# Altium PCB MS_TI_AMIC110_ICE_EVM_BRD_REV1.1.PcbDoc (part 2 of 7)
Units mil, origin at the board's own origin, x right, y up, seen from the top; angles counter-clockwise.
Board outline 3464.57 x 2204.72 mil, 8 copper layers (TopLayer - S1 (.GTL), MidLayer1 - S2 (.G1), MidLayer2 - S3 (.G2), MidLayer3 - S4 (.G3), MidLayer4 - S5 (.G4), MidLayer5 - S6 (.G5), MidLayer6 - S7 (.G6), BottomLayer - S8 (.GBL)), stack 58.937 mil thick; 504 components, 369 nets, 1811 pads, 874 vias.
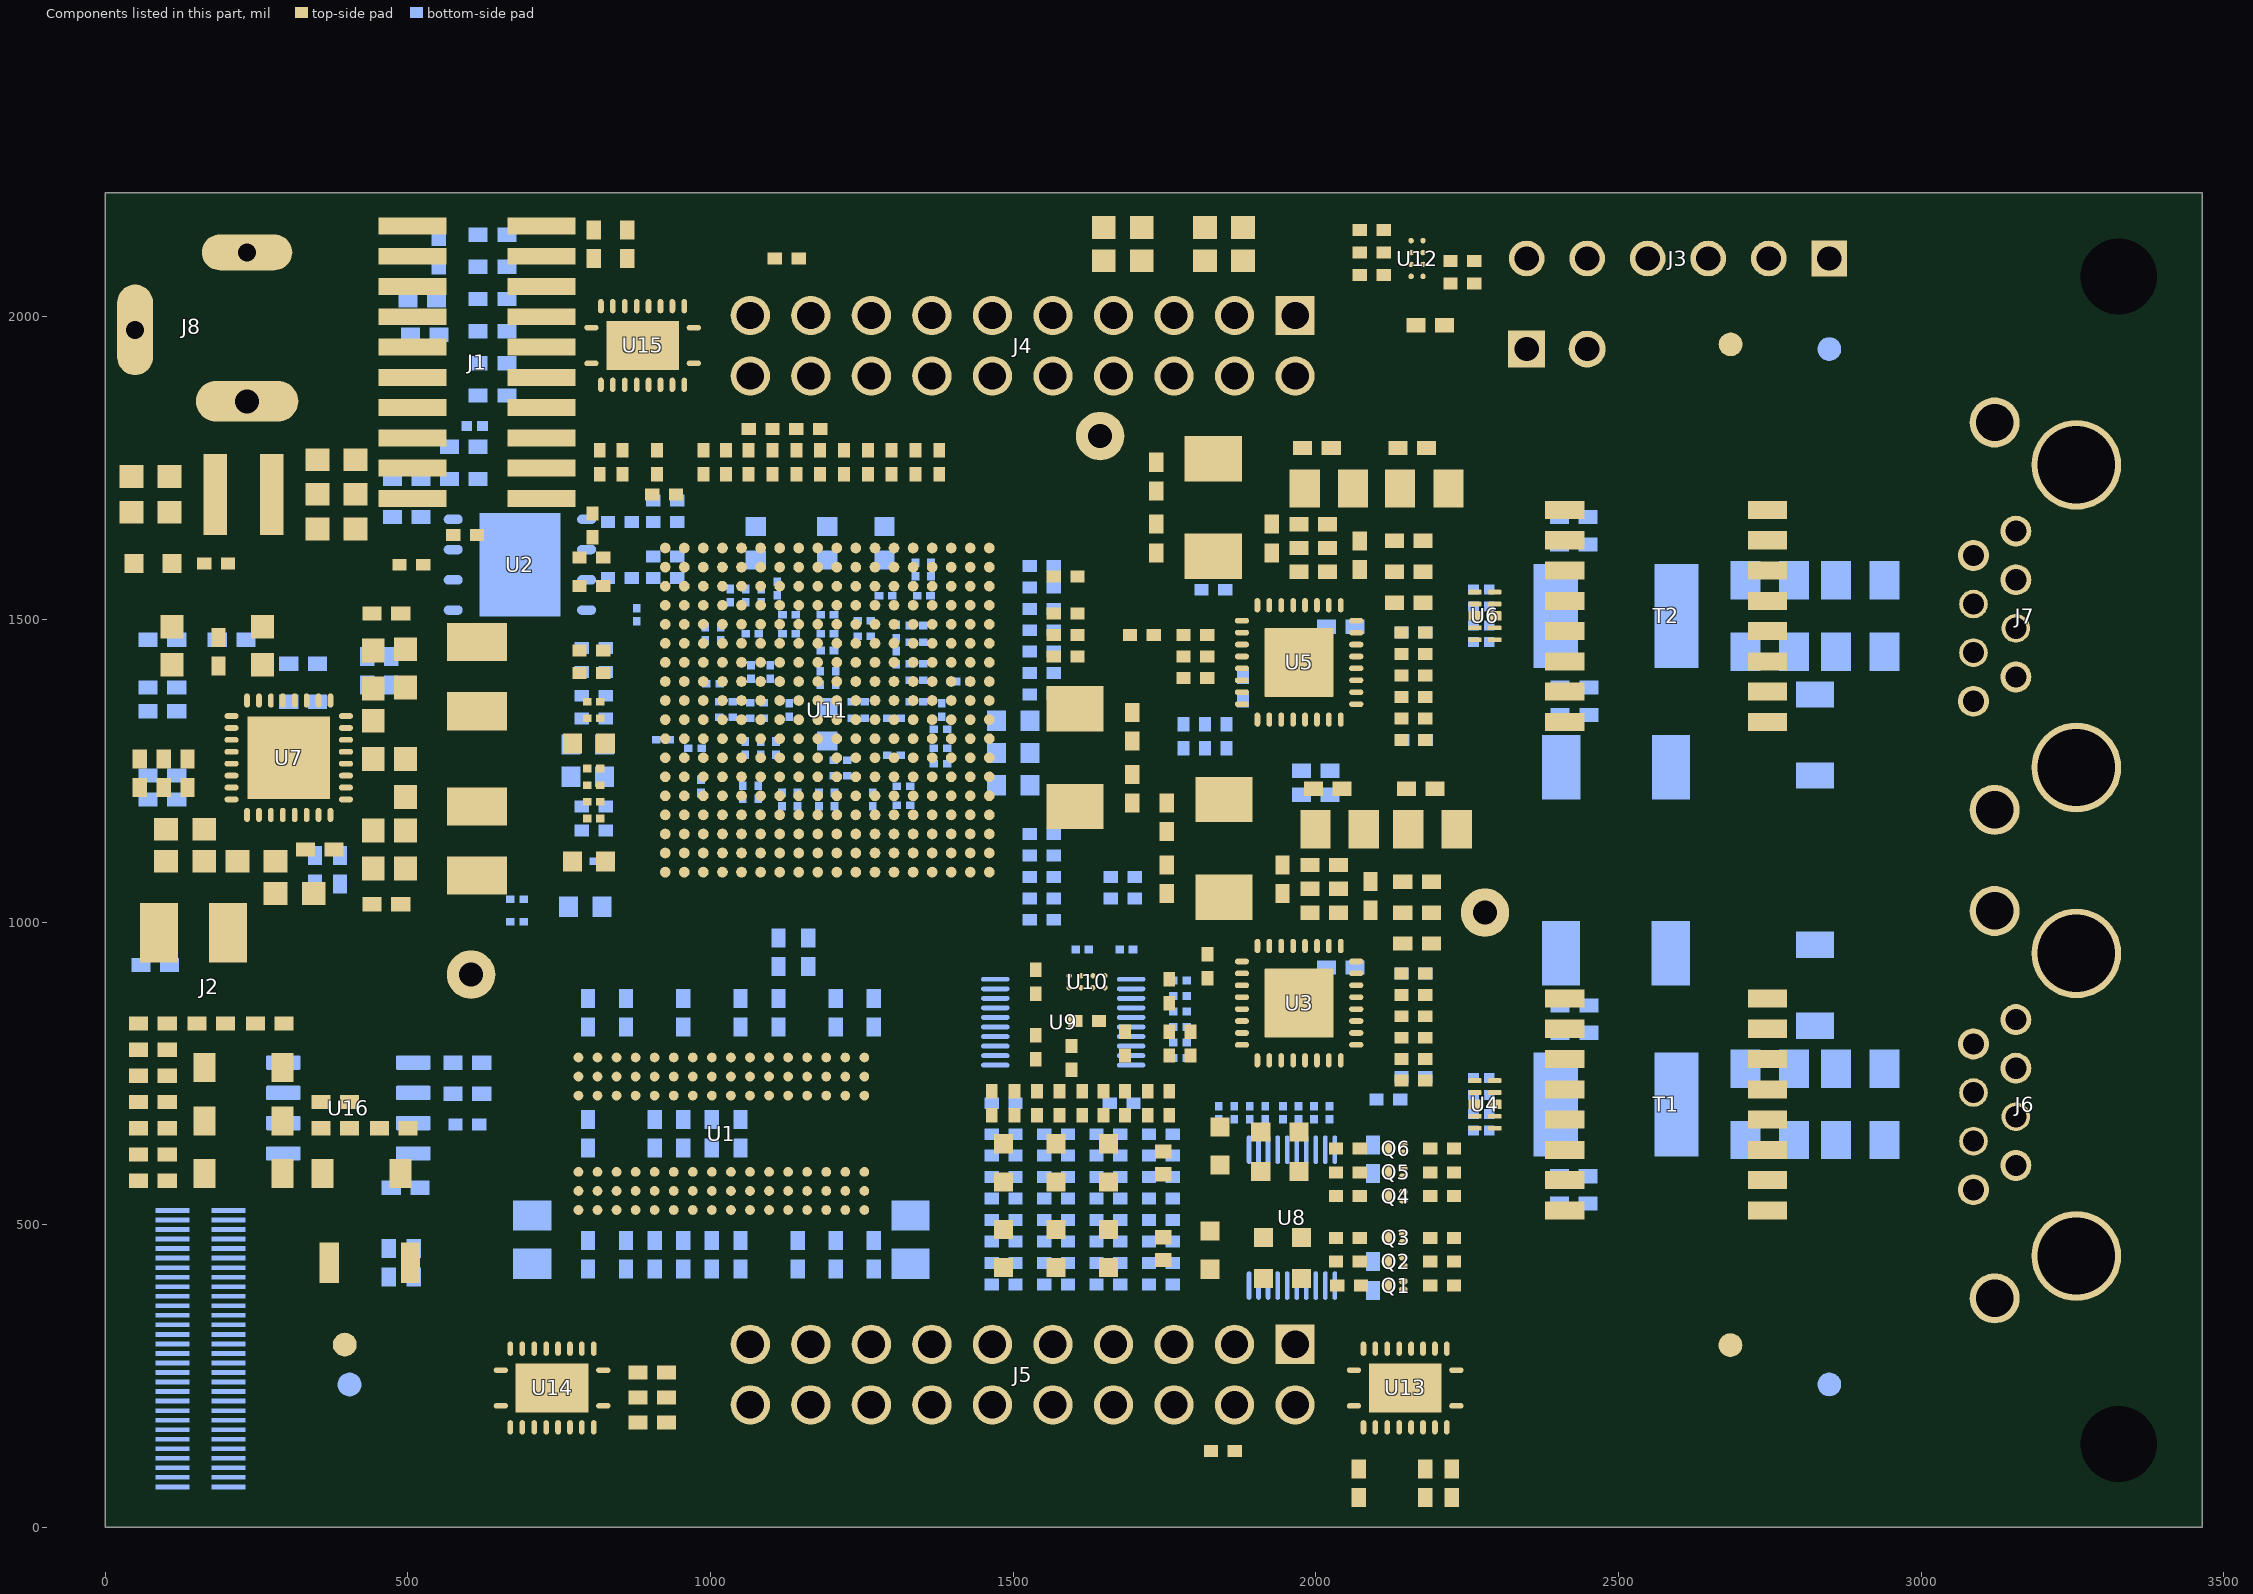
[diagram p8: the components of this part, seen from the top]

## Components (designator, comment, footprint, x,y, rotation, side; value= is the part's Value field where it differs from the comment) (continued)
R119 "CRCW040210K0JNED" 0402 2094.49,415.35 r270 bottom value=10k
R120 "CRCW040210K0JNED" 0402L 1484.25,700.79 r180 bottom value=10k
R121 "CRCW040210K0JNED" 0402L 1537.4,901.57 r90 top value=10k
R122 "CRCW0402100KJNED" 0402L 1570.87,401.57 r180 bottom value=100k
R123 "CRCW0402100KJNED" 0402L 1657.48,401.57 r0 bottom value=100k
R124 "CRCW0402100KJNED" 0402L 1570.87,437.01 r180 bottom value=100k
R125 "CRCW0402100KJNED" 0402L 1657.48,437.01 r0 bottom value=100k
R126 "CRCW0402100KJNED" 0402L 1570.87,472.44 r180 bottom value=100k
R127 "CRCW0402100KJNED" 0402L 1657.48,472.44 r0 bottom value=100k
R128 "CRCW0402100KJNED" 0402L 1570.87,507.87 r180 bottom value=100k
R129 "CRCW0402100KJNED" 0402L 1657.48,507.87 r0 bottom value=100k
R130 "CRCW0402100KJNED" 0402L 1570.87,543.31 r180 bottom value=100k
R131 "CRCW0402100KJNED" 0402L 1657.48,543.31 r0 bottom value=100k
R132 "CRCW0402100KJNED" 0402L 1570.87,578.74 r180 bottom value=100k
R133 "CRCW0402100KJNED" 0402L 1657.48,578.74 r0 bottom value=100k
R134 "CRCW0402100KJNED" 0402L 1570.87,614.17 r180 bottom value=100k
R135 "CRCW0402100KJNED" 0402L 1657.48,614.17 r0 bottom value=100k
R136 "CRCW0402100KJNED" 0402L 1570.87,649.61 r180 bottom value=100k
R137 "CRCW0402100KJNED" 0402L 1657.48,649.61 r0 bottom value=100k
R138 "CRCW040210K0JNED" 0402L 807.09,1374.02 r180 bottom value=10k
R139 "CRCW04020000Z0ED" 0402L 1220.47,1759.84 r90 top value=0
R140 "CRCW040222R0JNED" 0402L 1259.84,1759.84 r90 top value=22
R141 "CRCW040210K0JNED" 0402L 807.09,1151.57 r0 bottom value=10k
R142 "CRCW040210K0JNED" 0402L 807.09,1190.94 r0 bottom value=10k
R143 "CRCW04020000Z0ED" 0402L 1299.21,1759.84 r90 top value=0
R144 "CRCW04020000Z0ED" 0402L 1025.59,1759.84 r90 top value=0
R145 "CRCW040247R0JNED" 0402L 1141.73,1759.84 r90 top value=47
R146 "CRCW04020000Z0ED" 0402L 1338.58,1759.84 r90 top value=0
R147 "CRCW040222R0JNED" 0402L 1062.99,1759.84 r90 top value=22
R148 "CRCW040222R0JNED" 0402L 1181.1,1759.84 r90 top value=22
R149 "CRCW040247R0JNED" 0402L 803.15,1602.36 r0 top value=47
R150 "CRCW040222R0JNED" 0402L 1586.61,1474.41 r180 top value=22
R151 "CRCW04020000Z0ED" 0402L 1102.36,1759.84 r90 top value=0
R152 "CRCW04020000Z0ED" 0402L 803.15,1555.12 r0 top value=0
R153 "CRCW040222R0JNED" 0402L 1586.61,1509.84 r180 top value=22
R154 "CRCW04020000Z0ED" 0402L 1547.24,1003.94 r0 bottom value=0
R155 "CRCW04022K20JNED" 0402L 1586.61,1570.87 r0 top value=2.2k
R156 "CRCW04020000Z0ED" 0402L 1547.24,1110.24 r0 bottom locked value=0
R157 "CRCW04020000Z0ED" 0402L 1547.24,1145.67 r0 bottom locked value=0
R158 "CRCW04020000Z0ED" 0402L 1547.24,1039.37 r0 bottom locked value=0
R159 "CRCW04020000Z0ED" 0402L 1547.24,1074.8 r0 bottom locked value=0
R160 "CRCW04020000Z0ED" 0402L 1547.24,1588.58 r0 bottom value=0
R161 "CRCW04020000Z0ED" 0402L 1547.24,1411.42 r180 bottom value=0
R162 "CRCW040210K0JNED" 0402L 925.2,1696.85 r0 bottom value=10k
R163 "CRCW04020000Z0ED" 0402L 1547.24,1375.98 r180 bottom value=0
R164 "CRCW04020000Z0ED" 0402l 1547.24,1517.72 r0 bottom locked value=0
R165 "CRCW04020000Z0ED" 0402l 1547.24,1553.15 r0 bottom locked value=0
R166 "CRCW04020000Z0ED" 0402l 1547.24,1482.28 r0 bottom locked value=0
R167 "CRCW04020000Z0ED" 0402l 1547.24,1446.85 r0 bottom locked value=0
R168 "CRCW040210K0JNED" 0402L 925.2,1661.42 r0 bottom value=10k
R169 "CRCW040249R9FKED" 0402 1161.42,950.4 r90 bottom value=49.9
R170 "CRCW04020000Z0ED" 0402L 2242.13,2055.12 r180 top value=0
R171 "CRCW04020000Z0ED" 0402L 2092.52,2068.9 r0 top value=0
R172 "CRCW0402100KJNED" 0402L 2242.13,2092.52 r180 top value=100k
R173 "CRCW040251K0JNED" 0402 2181.1,72.83 r270 top value=51k
R174 "CRCW040233K0JNED" 0402 903.54,173.23 r180 top value=33k
R175 "CRCW040233K0JNED" 0402 862.2,2120.08 r90 top value=33k
R176 "CRCW040251K0JNED" 0402 2070.87,72.83 r90 top value=51k
R177 "CRCW040251K0JNED" 0402 903.54,255.91 r180 top value=51k
R178 "CRCW04023K30JNED" 0402L 183.07,1592.52 r0 top value=3.3k
R179 "CRCW040222R0JNED" 0402L 1377.95,1759.84 r90 top value=22
R180 "CRCW060310K0JNEA" 0603 1848.43,2092.52 r0 top value=10k
R181 "CRCW060310K0JNEA" 0603 1681.1,2092.52 r180 top value=10k
R182 "CRCW04020000Z0ED" 0402L 803.15,1448.82 r0 top value=0
R183 "CRCW04020000Z0ED" 0402L 803.15,1411.42 r180 top value=0
R184 "CRCW06031K00JNEA" 0603 1848.43,2147.64 r0 top value=1.0k
R185 "CRCW06031K00JNEA" 0603 1681.1,2147.64 r180 top value=1.0k
R186 "CRCW04020000Z0ED" 0402L 1846.46,125.98 r180 top value=0
R187 "CRCW04020000Z0ED" 0402L 1125.98,2096.46 r0 top value=0
R188 "CRCW04022K49FKED" 0402L 1537.4,793.31 r270 top value=2.49k
R189 "CRCW04022K49FKED" 0402L 1596.46,775.59 r270 top value=2.49k
R190 "CRCW04024K70JNED" 0402L 598.43,665.35 r0 bottom value=4.7k
R191 "CRCW02011K00FKED" 0201L 2022.64,685.04 r90 bottom value=1.00k
R192 "CRCW02011K00FKED" 0201L 1997.05,685.04 r90 bottom value=1.00k
R193 "CRCW02011K00FKED" 0201L 1971.46,685.04 r90 bottom value=1.00k
R194 "CRCW02011K00FKED" 0201L 1945.87,685.04 r90 bottom value=1.00k
R195 "CRCW02011K00FKED" 0201L 1916.34,685.04 r90 bottom value=1.00k
R196 "CRCW02011K00FKED" 0201L 1890.75,685.04 r90 bottom value=1.00k
R197 "CRCW02011K00FKED" 0201L 1839.57,685.04 r90 bottom value=1.00k
R198 "CRCW02011K00FKED" 0201L 1865.16,685.04 r90 bottom value=1.00k
R199 "CRCW02011K00FKED" 0201L 1775.59,775.59 r0 bottom value=1.00k
R200 "CRCW02011K00FKED" 0201L 1775.59,801.18 r0 bottom value=1.00k
R201 "CRCW02011K00FKED" 0201L 1775.59,826.77 r0 bottom value=1.00k
R202 "CRCW02011K00FKED" 0201L 1775.59,852.36 r0 bottom value=1.00k
R203 "CRCW02011K00FKED" 0201L 1614.17,954.72 r180 bottom value=1.00k
R204 "CRCW02011K00FKED" 0201L 1775.59,877.95 r0 bottom value=1.00k
R205 "CRCW02011K00FKED" 0201L 1775.59,903.54 r0 bottom value=1.00k
R206 "CRCW02011K00FKED" 0201L 1687.01,954.72 r180 bottom value=1.00k
R207 "CRCW040210K0JNED" 0402L 925.2,1604.33 r0 bottom value=10k
R208 "CRCW040210K0JNED" 0402L 925.2,1568.9 r0 bottom value=10k
R209 "CRCW040210K0JNED" 0402L 1681.1,1074.8 r0 bottom value=10k
R210 "CRCW040210K0JNED" 0402L 1681.1,1039.37 r0 bottom value=10k
R211 "CRCW04020000Z0ED" 0402L 1586.61,1438.98 r180 top value=0
R212 "CRCW04020000Z0ED" 0402L 1712.6,1474.41 r0 top value=0
R213 "CRCW040210K0JNED" 0402L 854.33,1759.84 r90 top value=10k
R214 "CRCW040210K0JNED" 0402L 923.23,1706.69 r180 top value=10k
R215 "CRCW04024K70JNED" 0402L 911.42,1759.84 r270 top value=4.7k
R216 "CRCW04024K70JNED" 0402L 988.19,1759.84 r90 top value=4.7k
R217 "CRCW040210K0FKED" 0402L 850.39,1661.42 r0 bottom value=10.0k
R218 "CRCW04024K70JNED" 0402 598.43,716.54 r0 bottom value=4.7k
R219 "CRCW04024K70JNED" 0402 598.43,767.72 r0 bottom value=4.7k
R220 "CRCW080575R0FKEA" 0805_HV 2899.61,757.87 r0 bottom value=75.0
R221 "CRCW080575R0FKEA" 0805_HV 2899.61,639.76 r0 bottom value=75.0
R222 "CRCW080575R0FKEA" 0805_HV 2750,639.76 r180 bottom value=75.0
R223 "CRCW080575R0FKEA" 0805_HV 2750,757.87 r180 bottom value=75.0
R224 "CRCW080575R0FKEA" 0805_HV 2899.61,1564.96 r0 bottom value=75.0
R225 "CRCW080575R0FKEA" 0805_HV 2899.61,1446.85 r0 bottom value=75.0
R226 "CRCW080575R0FKEA" 0805_HV 2750,1446.85 r180 bottom value=75.0
R227 "CRCW080575R0FKEA" 0805_HV 2750,1564.96 r180 bottom value=75.0
R228 "CRCW0201499RFKED" 0201L 807.09,1198.82 r0 top value=499
R229 "CRCW0201499RFKED" 0201L 807.09,1226.38 r0 top value=499
R230 "CRCW0201499RFKED" 0201L 807.09,1171.26 r0 top value=499
R231 "CRCW0201499RFKED" 0201L 807.09,1253.94 r0 top value=499
R232 "CRCW0201499RFKED" 0201L 807.09,1336.61 r0 top value=499
R233 "CRCW0201499RFKED" 0201L 807.09,1364.17 r0 top value=499
R234 "CRCW040210K0JNED" 0402L 816.93,1759.84 r270 top value=10k
R235 "CRCW04022K49FKED" 0402L 1685.04,799.21 r270 top value=2.49k
R236 "CRCW04022K49FKED" 0402L 1614.17,700.79 r90 top value=2.49k
R237 "CRCW04024K70JNED" 0402L 1801.18,1474.41 r0 top value=4.7k
R238 "CRCW040210K0FKED" 0402L 505.91,1590.55 r180 top value=10.0k
R239 "CRCW040210K0FKED" 0402L 805.12,1655.51 r90 top value=10.0k
R240 "CRCW040210K0FKED" 0402L 594.49,1639.76 r180 top value=10.0k
S1 "B3U-1000P" SW_B3U-1000P 437.01,437.01 r0 top
T1 "HX1188FNLT" Pulse_HX1188FNLT 2578.74,698.82 r0 top value=350uH
T2 "HX1188FNLT" Pulse_HX1188FNLT 2578.74,1505.91 r0 top value=350uH
TP8 "5001" Keystone5001#1 604.33,913.39 r90 top
TP9 "5001" Keystone5001#2 1643.7,1803.15 r90 top
TP10 "5001" Keystone5001#1 2279.53,1015.75 r90 top
U1 "MT41K256M16HA-125 IT:E" 96-FBGA 1017.95,650.41 r270 top
U2 "W25Q64FVZPIG" "Winbond-WSON6x5_Code P" 685.04,1590.55 r180 bottom
U3 "DP83822HRHBR" RHB0032B 1972.44,866.14 r90 top
U4 "TPD4E05U06DQAR" DQA0010A 2279.53,698.82 r0 top
U5 "DP83822HRHBR" RHB0032B 1972.44,1429.13 r90 top
U6 "TPD4E05U06DQAR" DQA0010A 2279.53,1505.91 r0 top
U7 "TPS650250RHBR" RHB0032E 303.15,1271.65 r180 top
U8 "SN74LVC541ADGVR" DGV0020A_L 1960.63,511.81 r90 bottom
U9 "SN74LVC541ADGVR" DGV0020A_L 1582.68,834.65 r0 bottom
U10 "SN74LVC2G66YZPR" YZP0008ADAD#1 1622.05,901.57 r270 top
U11 "AMIC110BZCZA" ZCZ0324A 1192.91,1350.39 r90 top
U12 "SN74LVC2G241YZPR" YZP0008ADAD#2 2167.32,2096.46 r180 top
U13 "SN74CB3Q3245RGYR" RGY0020A 2147.64,230.32 r270 top
U14 "SN74CB3Q3245RGYR" RGY0020A 738.19,230.32 r270 top
U15 "SN74CB3Q3245RGYR" RGY0020A 887.8,1952.76 r90 top
U16 "CAT24C256WI-GT3" SOIC-8 401.57,692.91 r0 bottom
Y1 "CTX1175TR-ND" XTAL_ABM3 1848.43,1122.05 r270 top
Y2 "CTX1175TR-ND" XTAL_ABM3 1830.71,1685.04 r270 top
Y3 "CTX1175TR-ND" XTAL_ABM3 1602.36,1271.65 r270 top
ZZ1 "This Assembly Note is for PCB labels only" AssemblyNoteLabel 209.98,3353.98 r0 top
ZZ2 "These assemblies are ESD sensitive, ESD precautions shall be observed." AssemblyNote 210.83,3260.47 r0 top
ZZ3 "These assemblies must be clean and free from flux and all contaminants. Use of no clean flux is not acceptable." AssemblyNote 209.44,3176.3 r0 top
ZZ4 "These assemblies must comply with workmanship standards IPC-A-610 Class 2, unless otherwise specified." AssemblyNote 209.42,3096.57 r0 top

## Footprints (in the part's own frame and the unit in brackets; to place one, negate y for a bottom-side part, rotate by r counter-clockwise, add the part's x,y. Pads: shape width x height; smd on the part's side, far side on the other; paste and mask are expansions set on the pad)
96-FBGA [mm] "BGA, 96-Balls, Body 9x14mm, Pitch 0.8mm"
  round 0.41 smd: A1(-3.2,6) A2(-2.4,6) A3(-1.6,6) A7(1.6,6) A8(2.4,6) A9(3.2,6) B1(-3.2,5.2) B2(-2.4,5.2) B3(-1.6,5.2) B7(1.6,5.2) B8(2.4,5.2) B9(3.2,5.2) C1(-3.2,4.4) C2(-2.4,4.4) C3(-1.6,4.4) C7(1.6,4.4) C8(2.4,4.4) C9(3.2,4.4) D1(-3.2,3.6) D2(-2.4,3.6) D3(-1.6,3.6) D7(1.6,3.6) D8(2.4,3.6) D9(3.2,3.6) E1(-3.2,2.8) E2(-2.4,2.8) E3(-1.6,2.8) E7(1.6,2.8) E8(2.4,2.8) E9(3.2,2.8) F1(-3.2,2) F2(-2.4,2) F3(-1.6,2) F7(1.6,2) F8(2.4,2) F9(3.2,2) G1(-3.2,1.2) G2(-2.4,1.2) G3(-1.6,1.2) G7(1.6,1.2) G8(2.4,1.2) G9(3.2,1.2) H1(-3.2,0.4) H2(-2.4,0.4) H3(-1.6,0.4) H7(1.6,0.4) H8(2.4,0.4) H9(3.2,0.4) J1(-3.2,-0.4) J2(-2.4,-0.4) J3(-1.6,-0.4) J7(1.6,-0.4) J8(2.4,-0.4) J9(3.2,-0.4) K1(-3.2,-1.2) K2(-2.4,-1.2) K3(-1.6,-1.2) K7(1.6,-1.2) K8(2.4,-1.2) K9(3.2,-1.2) L1(-3.2,-2) L2(-2.4,-2) L3(-1.6,-2) L7(1.6,-2) L8(2.4,-2) L9(3.2,-2) M1(-3.2,-2.8) M2(-2.4,-2.8) M3(-1.6,-2.8) M7(1.6,-2.8) M8(2.4,-2.8) M9(3.2,-2.8) N1(-3.2,-3.6) N2(-2.4,-3.6) N3(-1.6,-3.6) N7(1.6,-3.6) N8(2.4,-3.6) N9(3.2,-3.6) P1(-3.2,-4.4) P2(-2.4,-4.4) P3(-1.6,-4.4) P7(1.6,-4.4) P8(2.4,-4.4) P9(3.2,-4.4) R1(-3.2,-5.2) R2(-2.4,-5.2) R3(-1.6,-5.2) R7(1.6,-5.2) R8(2.4,-5.2) R9(3.2,-5.2) T1(-3.2,-6) T2(-2.4,-6) T3(-1.6,-6) T7(1.6,-6) T8(2.4,-6) T9(3.2,-6)
  silkscreen extent -5.27,-7 4.5,7, body extent -4.5,-7 4.5,7, height 1.21
0201 [mm] "Data from Kemet datasheet CC101_COM dated 7/28/11"
  rect 0.46x0.42 smd mask+0.048: 1(-0.33,0) 2(0.33,0)
  body extent -0.31,-0.16 0.31,0.16, height 0.26
0201L [mm] "Data from Kemet datasheet CC101_COM dated 7/28/11"
  rect 0.36x0.32 smd mask+0.048: 1(-0.28,0) 2(0.28,0)
  body extent -0.31,-0.16 0.31,0.16, height 0.26
0402 [mm] "0402 from SM-752 data"
  rect 0.8x0.6 smd: 1(-0.6,0) 2(0.6,0)
  silkscreen extent -1.22,-0.52 1.22,0.52, body extent -0.55,-0.3 0.55,0.3, height 0.6
0402L [mm] "0402 from SM-752 data"
  rect 0.6x0.5 smd: 1(-0.5,0) 2(0.5,0)
  body extent -0.55,-0.3 0.55,0.3, height 0.6
0402l [mm] "0402 from SM-752 data"
  rect 0.6x0.5 smd: 1(-0.5,0) 2(0.5,0)
  body extent -0.55,-0.3 0.55,0.3, height 0.6
0603 [mm] "0603 from SM-752 data"
  rect 1x0.95 smd: 1(-0.8,0) 2(0.8,0)
  silkscreen extent -1.52,-0.69 1.52,0.69, body extent -0.87,-0.47 0.87,0.47, height 1
0603L [mm] "0603 from SM-752 data"
  rect 0.8x0.85 smd: 1(-0.7,0) 2(0.7,0)
  silkscreen extent -0.07,-0.33 0.07,0.33, body extent -0.87,-0.47 0.87,0.47, height 1
0805_HV [mil] "0805 with 30mil clearance between pads"
  rect 50x63 smd: 1(-40,0) 2(40,0)
  silkscreen extent -74,-40 74,40, body extent -43,-29 43,29, height 57
1206_190 [mm] "1206_190"
  rect 1.1x1.6 smd: 1(-1.7,0) 2(1.7,0)
  silkscreen extent -0.9,-1 0.9,1, body extent -1.75,-0.95 1.75,0.95, height 1.9
1812_180 [mm] "SMT, 2-Leads, Body 4.5x3.2mm"
  rect 1.85x4.36 smd: 1(-2.53,0) 2(2.53,0)
  silkscreen extent -3.75,-2.48 3.75,2.48, body extent -2.43,-1.75 2.42,1.75, height 1.8
2010 [mm] "Chip Capacitor, Body 5.08x2.54mm, IPC Medium Density"
  rect 1.6x2.7 smd: 1(-2.3,0) 2(2.3,0)
  silkscreen extent -3.42,-1.65 3.42,1.65, body extent -2.73,-1.45 2.73,1.45, height 1.66
APTD1608 [mm] "Kingbright"
  rect 0.8x0.8 smd: 1(-0.8,0) 2(0.8,0)
  silkscreen extent -1.9,-0.8 1.2,0.8, body extent -0.88,-0.49 0.88,0.49, height 0.95
AssemblyNote [mil] "Assembly Note"
AssemblyNoteLabel [mil] "Assembly Note for PCB Labels"
CONN_RAPC722X [mm] "Conn_DC Jack"
  oval 1.7x4.3 hole 1.01 slot 3.56 at 90 deg: 1(-13.741,0)
  oval 1.5x3.8 hole 0.76 slot 3.05 at 90 deg: 2(-7.493,0)
  oval 3.8x1.5 hole 0.76 slot 3.05 at 0 deg: 3(-10.744,4.7)
  silkscreen extent -14.48,-4.57 0.25,4.57, body extent -14.5,-4.57 0.23,4.83, height 11.18
CONN_SSW-110-23-F-D [mm] "SAMTEC"
  rect 1.65x1.65 / inner rect 1.4x1.4 / far side rect 1.65x1.65 hole 1.15: 1(11.43,-1.27)
  round 1.65 / inner round 1.4 / far side round 1.65 hole 1.15: 2(11.43,1.27) 3(8.89,-1.27) 4(8.89,1.27) 5(6.35,-1.27) 6(6.35,1.27) 7(3.81,-1.27) 8(3.81,1.27) 9(1.27,-1.27) 10(1.27,1.27) 11(-1.27,-1.27) 12(-1.27,1.27) 13(-3.81,-1.27) 14(-3.81,1.27) 15(-6.35,-1.27) 16(-6.35,1.27) 17(-8.89,-1.27) 18(-8.89,1.27) 19(-11.43,-1.27) 20(-11.43,1.27)
  silkscreen extent -13.08,-2.46 13.08,2.54, body extent -13,-2.51 13,2.54, height 8.59
DGV0020A_L [mm] "TSSOP, 20-Leads, Body 5x4.4mm, Pitch 0.4mm, IPC High Density"
  oval 1.2x0.2 smd: 1(-2.85,1.8) 2(-2.85,1.4) 3(-2.85,1) 4(-2.85,0.6) 5(-2.85,0.2) 6(-2.85,-0.2) 7(-2.85,-0.6) 8(-2.85,-1) 9(-2.85,-1.4) 10(-2.85,-1.8) 11(2.85,-1.8) 12(2.85,-1.4) 13(2.85,-1) 14(2.85,-0.6) 15(2.85,-0.2) 16(2.85,0.2) 17(2.85,0.6) 18(2.85,1) 19(2.85,1.4) 20(2.85,1.8)
  silkscreen extent -3.35,-2.55 1.85,2.55, body extent -3.21,-2.5 3.21,2.5, height 1.2
DQA0010A [mm] "SON, 10-Leads, Body 1x2.5mm, Pitch 0.5mm, TI Recommended"
  rrect50% 0.565x0.2 smd: 1(-0.417,1) 2(-0.417,0.5) 4(-0.417,-0.5) 5(-0.417,-1) 6(0.417,-1) 7(0.417,-0.5) 9(0.417,0.5) 10(0.417,1)
  rrect28% 0.565x0.36 on Top Paste: 3(-0.417,0) 8(0.417,0)
  rrect25% 0.565x0.4 smd paste-0.2: 3(-0.417,0) 8(0.417,0)
  silkscreen extent -0.67,-1.45 0.55,1.45, body extent -0.55,-1.3 0.55,1.3, height 0.56
ESD_Overlay_Small [mil]
  silkscreen extent -62,-48 64,61
FCC_disclaimer [mil]
Fiducial10-20 [mm]
  round 1 smd mask+0.5: 1(0,0)
  TopLayer - S1 (.GTL) keep-out circle w1.178: c0,0 r0.5
Hirose_DF40HC-4_0-60DS-0_4V [mm] "Receptacle, 0.4mm, 30x2, SMT"
  rect 0.2x1.43 smd mask-1: 1(-5.8,1.175) 2(-5.8,-1.175) 3(-5.4,1.175) 4(-5.4,-1.175) 5(-5,1.175) 6(-5,-1.175) 7(-4.6,1.175) 8(-4.6,-1.175) 9(-4.2,1.175) 10(-4.2,-1.175) 11(-3.8,1.175) 12(-3.8,-1.175) 13(-3.4,1.175) 14(-3.4,-1.175) 15(-3,1.175) 16(-3,-1.175) 17(-2.6,1.175) 18(-2.6,-1.175) 19(-2.2,1.175) 20(-2.2,-1.175) 21(-1.8,1.175) 22(-1.8,-1.175) 23(-1.4,1.175) 24(-1.4,-1.175) 25(-1,1.175) 26(-1,-1.175) 27(-0.6,1.175) 28(-0.6,-1.175) 29(-0.2,1.175) 30(-0.2,-1.175) 31(0.2,1.175) 32(0.2,-1.175) 33(0.6,1.175) 34(0.6,-1.175) 35(1,1.175) 36(1,-1.175) 37(1.4,1.175) 38(1.4,-1.175) 39(1.8,1.175) 40(1.8,-1.175) 41(2.2,1.175) 42(2.2,-1.175) 43(2.6,1.175) 44(2.6,-1.175) 45(3,1.175) 46(3,-1.175) 47(3.4,1.175) 48(3.4,-1.175) 49(3.8,1.175) 50(3.8,-1.175) 51(4.2,1.175) 52(4.2,-1.175) 53(4.6,1.175) 54(4.6,-1.175) 55(5,1.175) 56(5,-1.175) 57(5.4,1.175) 58(5.4,-1.175) 59(5.8,1.175) 60(5.8,-1.175)
  round 4.3 on Bottom Solder: ""(36.195,1.905)
  silkscreen extent -7.3,-1.47 7.3,1.8, body extent -7.3,-1.69 7.3,1.69, height 3.9
Keystone5001#1 [mil] "For Keystone 500x miniature loop terminals"
  round 80 hole 40: 1(0,0)
  silkscreen extent -58,-58 58,58, body extent -49,-49 49,49, height 182
Keystone5001#2 [mil] "For Keystone 500x miniature loop terminals"
  round 80 / inner round 55.12 / far side round 80 hole 40: 1(0,0)
  silkscreen extent -58,-58 58,58, body extent -49,-49 49,49, height 182
LABEL_650X200 [mil] "Thermal Transfer Label"
  round 1 on Mech13: 0(0,0)
  silkscreen extent -325,-100 606,121, body extent -325,-100 475,100, height 1
"NY PMS 440 0025 PH" [mm] "4-40 nylon screw and mounting hole"
  round 0.1 hole 3.2 unplated mask+1.85: 1(0,0)
  body extent -3.3,-3.3 3.3,3.3, height 2.69
Pb-Free_Overlay_Small [mil]
  silkscreen extent -46,-46 46,46
Pulse_HX1188FNLT [mm] "SMD, 16-Leads, Body 12.7x9.09mm, Pitch 1.27mm"
  rect 1.65x0.76 smd: 1(-4.255,4.445) 2(-4.255,3.175) 3(-4.255,1.905) 4(-4.255,0.635) 5(-4.255,-0.635) 6(-4.255,-1.905) 7(-4.255,-3.175) 8(-4.255,-4.445) 9(4.255,-4.445) 10(4.255,-3.175) 11(4.255,-1.905) 12(4.255,-0.635) 13(4.255,0.635) 14(4.255,1.905) 15(4.255,3.175) 16(4.255,4.445)
  silkscreen extent -4.87,-6.42 4.61,6.42, body extent -4.65,-6.42 4.65,6.42, height 6.13
RGY0020A [mm] "QFN, 20-Leads, Body 4.5x3.5mm, Pitch 0.5mm, Thermal Pad 3.05x2.05mm, TI Recommended"
  oval 0.24x0.6 smd: 1(-0.75,2.15) 10(-0.75,-2.15) 11(0.75,-2.15) 20(0.75,2.15)
  oval 0.6x0.24 smd: 2(-1.65,1.75) 3(-1.65,1.25) 4(-1.65,0.75) 5(-1.65,0.25) 6(-1.65,-0.25) 7(-1.65,-0.75) 8(-1.65,-1.25) 9(-1.65,-1.75) 12(1.65,-1.75) 13(1.65,-1.25) 14(1.65,-0.75) 15(1.65,-0.25) 16(1.65,0.25) 17(1.65,0.75) 18(1.65,1.25) 19(1.65,1.75)
  rect 2.05x3.05 smd paste-1.025: 21(0,0)
  silkscreen extent -1.97,-2.47 1.97,2.47, body extent -1.75,-2.25 1.75,2.25, height 1
RHB0032B [mm] "QFN, 32-Leads, Body 5x5mm, Pitch 0.5mm, Thermal Pad 2.9x2.9mm"
  rrect100% 0.6x0.24 smd: 1(-2.4,1.75) 2(-2.4,1.25) 3(-2.4,0.75) 4(-2.4,0.25) 5(-2.4,-0.25) 6(-2.4,-0.75) 7(-2.4,-1.25) 8(-2.4,-1.75) 17(2.4,-1.75) 18(2.4,-1.25) 19(2.4,-0.75) 20(2.4,-0.25) 21(2.4,0.25) 22(2.4,0.75) 23(2.4,1.25) 24(2.4,1.75)
  rrect100% 0.24x0.6 smd: 9(-1.75,-2.4) 10(-1.25,-2.4) 11(-0.75,-2.4) 12(-0.25,-2.4) 13(0.25,-2.4) 14(0.75,-2.4) 15(1.25,-2.4) 16(1.75,-2.4) 25(1.75,2.4) 26(1.25,2.4) 27(0.75,2.4) 28(0.25,2.4) 29(-0.25,2.4) 30(-0.75,2.4) 31(-1.25,2.4) 32(-1.75,2.4)
  rrect3% 2.9x2.9 smd paste-1.725: 33(0,0)
  silkscreen extent -2.72,-2.73 2.72,2.72, body extent -2.57,-2.58 2.58,2.57, height 1.01
RHB0032E [mm] "QFN, 32-Leads, Body 5x5mm, Pitch 0.5mm, Thermal Pad 3.45x3.45mm, TI Recommended"
  oval 0.6x0.24 smd: 1(-2.4,1.75) 2(-2.4,1.25) 3(-2.4,0.75) 4(-2.4,0.25) 5(-2.4,-0.25) 6(-2.4,-0.75) 7(-2.4,-1.25) 8(-2.4,-1.75) 17(2.4,-1.75) 18(2.4,-1.25) 19(2.4,-0.75) 20(2.4,-0.25) 21(2.4,0.25) 22(2.4,0.75) 23(2.4,1.25) 24(2.4,1.75)
  oval 0.24x0.6 smd: 9(-1.75,-2.4) 10(-1.25,-2.4) 11(-0.75,-2.4) 12(-0.25,-2.4) 13(0.25,-2.4) 14(0.75,-2.4) 15(1.25,-2.4) 16(1.75,-2.4) 25(1.75,2.4) 26(1.25,2.4) 27(0.75,2.4) 28(0.25,2.4) 29(-0.25,2.4) 30(-0.75,2.4) 31(-1.25,2.4) 32(-1.75,2.4)
  rect 3.45x3.45 smd paste-1.725: 33(0,0)
  silkscreen extent -2.72,-2.73 2.72,2.73, body extent -2.57,-2.57 2.58,2.58, height 1.01
Samtec_FTR-110-51-x-D-06 [mm] "Header, 1.27mm, 10x2, SMT"
  rect 2.87x0.711 smd: 1(-2.705,5.715) 2(2.705,5.715) 3(-2.705,4.445) 4(2.705,4.445) 5(-2.705,3.175) 6(2.705,3.175) 7(-2.705,1.905) 8(2.705,1.905) 9(-2.705,0.635) 10(2.705,0.635) 11(-2.705,-0.635) 12(2.705,-0.635) 13(-2.705,-1.905) 14(2.705,-1.905) 15(-2.705,-3.175) 16(2.705,-3.175) 17(-2.705,-4.445) 18(2.705,-4.445) 19(-2.705,-5.715) 20(2.705,-5.715)
  silkscreen extent -2.49,-6.35 2.49,6.7, body extent -3.76,-6.35 3.76,6.35, height 8.64
SOD-123 [mm] "On Semi recommended land pattern"
  rect 0.915x1.22 smd: 1(-1.637,0) 2(1.637,0)
  silkscreen extent -2.74,-1.17 2.03,1.17, body extent -1.93,-0.9 1.93,0.9, height 1.35
SOIC-8 [mm] "duplicate of SO-8.  SOIC, 8-Leads, Body 5.0x4.0mm (max), Pitch 1.27mm, IPC Medium Density"
  rrect17% 1.45x0.6 smd: 1(-2.725,1.905) 2(-2.725,0.635) 3(-2.725,-0.635) 4(-2.725,-1.905) 5(2.725,-1.905) 6(2.725,-0.635) 7(2.725,0.635) 8(2.725,1.905)
  silkscreen extent -3.5,-2.5 0.9,2.5, body extent -3,-2.45 3,2.45, height 1.63
Sullins_PEC06SAAN [mm] "TH, 6-Leads, Body 608x100mil, Pitch 100mil"
  rect 1.5x1.5 hole 1.016: 1(-6.35,0)
  round 1.5 hole 1.016: 2(-3.81,0) 3(-1.27,0) 4(1.27,0) 5(3.81,0) 6(6.35,0)
  silkscreen extent -7.72,-2.2 7.72,1.27, body extent -7.72,-1.27 7.72,1.27, height 8.59
Sullins_PxC01DAAN [mm] "Header, 2.54mm, 1x2, TH"
  rect 1.55x1.55 hole 1.016: 1(-1.27,0)
  round 1.55 hole 1.016: 2(1.27,0)
  silkscreen extent -2.9,-1.53 2.61,1.53, body extent -2.61,-1.53 2.61,1.53, height 8.71
SW_B3U-1000P [mm] "OMRON"
  rect 0.8x1.7 smd: 1(-1.7,0) 2(1.7,0)
  silkscreen extent -1.5,-1.25 1.5,1.25, body extent -1.5,-1.25 1.5,1.25, height 1.75
TEC_1-406541-1 [mm] "TE Connectivity"
  round 1.3 / inner round 1.4 / far side round 1.4 hole 0.89: 1(3.56,-0.18) 2(2.54,1.6) 3(1.52,-0.18) 7(-2.56,-0.18) 8(-3.58,1.6)
  round 1.2 / inner round 1.4 / far side round 1.4 hole 0.89: 4(0.5,1.6) 5(-0.52,-0.18) 6(-1.54,1.6)
  round 2.1 hole 1.57: 9(8.12,0.71) 10(-8.14,0.71)
  round 3.759 hole 3.251: 11(6.34,-2.72) 12(-6.36,-2.72)
  silkscreen extent -9.69,-8 9.69,8.06, body extent -9.33,-8 9.31,7.75, height 14.8
VLCF4020 [mm] "TDK"
  rect 1.6x2.5 smd: 1(-1.45,0) 2(1.45,0)
  TopLayer - S1 (.GTL) region: 0.65,-1.95 1.55,-1.95 2.25,-1.25 2.25,-1.15 0.65,-1.15
  TopLayer - S1 (.GTL) region: 0.65,1.95 1.55,1.95 2.25,1.25 2.25,1.15 0.65,1.15
  TopLayer - S1 (.GTL) region: -0.65,1.95 -1.55,1.95 -2.25,1.25 -2.25,1.15 -0.65,1.15
  TopLayer - S1 (.GTL) region: -0.65,-1.95 -1.55,-1.95 -2.25,-1.25 -2.25,-1.15 -0.65,-1.15
  silkscreen extent -0.4,-2.1 0.4,2.1, body extent -2.05,-2.05 2.05,2.05, height 2
VLMx1500_Orange [mm] "Vishay"
  rect 0.6x0.7 smd: 1(-0.475,0) 2(0.475,0)
  silkscreen extent 0.93,-0.32 1.13,0.33, body extent -0.6,-0.35 0.6,0.35, height 0.56
"Winbond-WSON6x5_Code P" [mm] "Winbond recommended land pattern"
  oval 0.8x0.4 smd: 1(-2.8,1.905) 2(-2.8,0.635) 3(-2.8,-0.635) 4(-2.8,-1.905) 5(2.8,-1.905) 6(2.8,-0.635) 7(2.8,0.635) 8(2.8,1.905)
  rect 3.4x4.35 smd: 9(0,0)
  silkscreen extent -3.84,-2.65 3.15,2.9, body extent -3.05,-2.55 3.05,2.55, height 0.8
WL-SMCW_GREEN [mm] "WURTH"
  rect 0.8x0.8 smd: 1(-0.8,0) 2(0.8,0)
  silkscreen extent -1.9,-0.8 1.2,0.8, body extent -0.85,-0.45 0.85,0.45, height 0.8
WL-SMCW_RED [mm] "WURTH"
  rect 0.8x0.8 smd: 1(-0.8,0) 2(0.8,0)
  silkscreen extent -1.9,-0.8 1.2,0.8, body extent -0.85,-0.45 0.85,0.45, height 0.8
WL-SMCW_YELLOW [mm] "WURTH"
  rect 0.8x0.8 smd: 1(-0.8,0) 2(0.8,0)
  silkscreen extent -1.9,-0.8 1.2,0.8, body extent -0.85,-0.45 0.85,0.45, height 0.8
XFL4020 [mm] "Coilcraft XFL4020 7/18/12"
  rect 0.98x3.4 smd: 1(-1.181,0) 2(1.181,0)
  silkscreen extent -2.16,-2.16 2.16,2.16, body extent -2.15,-2.15 2.15,2.15, height 2.1
XTAL_ABM3 [mm] "Abracon recommended land pattern 12.28.10"
  rect 1.9x2.4 smd: 1(-2.05,0) 2(2.05,0)
  silkscreen extent -2.67,-1.78 2.67,1.78, body extent -2.6,-1.7 2.6,1.7, height 1.3
YJC0003A [mm] "TI"
  rrect50% 0.25x0.2 on Top Paste: 0(-0.325,0.2) 0(-0.325,-0.2)
  rrect80% 0.35x0.25 smd paste-0.13 mask-0.05: 1(-0.325,0.175) 2(-0.325,-0.175)
  rrect57% 0.35x0.6 smd paste-0.05 mask-0.05: 3(0.325,0)
  body extent -0.5,-0.3 0.5,0.3, height 0.35
YZP0008ADAD#1 [mm] "BGA, 8-Leads, Body 1.9x0.9mm, Pitch 0.5mm"
  round 0.225 smd paste-0.12: A1(-0.25,0.75) A2(0.25,0.75) B1(-0.25,0.25) B2(0.25,0.25) C1(-0.25,-0.25) C2(0.25,-0.25) D1(-0.25,-0.75) D2(0.25,-0.75)
  silkscreen extent -0.6,-1.1 0.6,1.1, body extent -0.46,-0.96 0.46,0.96, height 0.51
YZP0008ADAD#2 [mm] "BGA, 8-Leads, Body 1.9x0.9mm, Pitch 0.5mm"
  round 0.23 smd paste-0.12: A1(-0.25,0.75) A2(0.25,0.75) B1(-0.25,0.25) B2(0.25,0.25) C1(-0.25,-0.25) C2(0.25,-0.25) D1(-0.25,-0.75) D2(0.25,-0.75)
  silkscreen extent -0.6,-1.1 0.6,1.1, body extent -0.46,-0.96 0.46,0.96, height 0.51
ZCZ0324A [mm] "BGA, 324-Balls, Body 15x15mm, Pitch 0.8mm"
  round 0.45 smd: A1(-6.8,6.8) A2(-6,6.8) A3(-5.2,6.8) A4(-4.4,6.8) A5(-3.6,6.8) A6(-2.8,6.8) A7(-2,6.8) A8(-1.2,6.8) A9(-0.4,6.8) A10(0.4,6.8) A11(1.2,6.8) A12(2,6.8) A13(2.8,6.8) A14(3.6,6.8) A15(4.4,6.8) A16(5.2,6.8) A17(6,6.8) A18(6.8,6.8) B1(-6.8,6) B2(-6,6) B3(-5.2,6) B4(-4.4,6) B5(-3.6,6) B6(-2.8,6) B7(-2,6) B8(-1.2,6) B9(-0.4,6) B10(0.4,6) B11(1.2,6) B12(2,6) B13(2.8,6) B14(3.6,6) B15(4.4,6) B16(5.2,6) B17(6,6) B18(6.8,6) C1(-6.8,5.2) C2(-6,5.2) C3(-5.2,5.2) C4(-4.4,5.2) C5(-3.6,5.2) C6(-2.8,5.2) C7(-2,5.2) C8(-1.2,5.2) C9(-0.4,5.2) C10(0.4,5.2) C11(1.2,5.2) C12(2,5.2) C13(2.8,5.2) C14(3.6,5.2) C15(4.4,5.2) C16(5.2,5.2) C17(6,5.2) C18(6.8,5.2) D1(-6.8,4.4) D2(-6,4.4) D3(-5.2,4.4) D4(-4.4,4.4) D5(-3.6,4.4) D6(-2.8,4.4) D7(-2,4.4) D8(-1.2,4.4) D9(-0.4,4.4) D10(0.4,4.4) D11(1.2,4.4) D12(2,4.4) D13(2.8,4.4) D14(3.6,4.4) D15(4.4,4.4) D16(5.2,4.4) D17(6,4.4) D18(6.8,4.4) E1(-6.8,3.6) E2(-6,3.6) E3(-5.2,3.6) E4(-4.4,3.6) E5(-3.6,3.6) E6(-2.8,3.6) E7(-2,3.6) E8(-1.2,3.6) E9(-0.4,3.6) E10(0.4,3.6) E11(1.2,3.6) E12(2,3.6) E13(2.8,3.6) E14(3.6,3.6) E15(4.4,3.6) E16(5.2,3.6) E17(6,3.6) E18(6.8,3.6) F1(-6.8,2.8) F2(-6,2.8) F3(-5.2,2.8) F4(-4.4,2.8) F5(-3.6,2.8) F6(-2.8,2.8) F7(-2,2.8) F8(-1.2,2.8) F9(-0.4,2.8) F10(0.4,2.8) F11(1.2,2.8) F12(2,2.8) F13(2.8,2.8) F14(3.6,2.8) F15(4.4,2.8) F16(5.2,2.8) F17(6,2.8) F18(6.8,2.8) G1(-6.8,2) G2(-6,2) G3(-5.2,2) G4(-4.4,2) G5(-3.6,2) G6(-2.8,2) G7(-2,2) G8(-1.2,2) G9(-0.4,2) G10(0.4,2) G11(1.2,2) G12(2,2) G13(2.8,2) G14(3.6,2) G15(4.4,2) G16(5.2,2) G17(6,2) G18(6.8,2) H1(-6.8,1.2) H2(-6,1.2) H3(-5.2,1.2) H4(-4.4,1.2) H5(-3.6,1.2) H6(-2.8,1.2) H7(-2,1.2) H8(-1.2,1.2) H9(-0.4,1.2) H10(0.4,1.2) H11(1.2,1.2) H12(2,1.2) H13(2.8,1.2) H14(3.6,1.2) H15(4.4,1.2) H16(5.2,1.2) H17(6,1.2) H18(6.8,1.2) J1(-6.8,0.4) J2(-6,0.4) J3(-5.2,0.4) J4(-4.4,0.4) J5(-3.6,0.4) J6(-2.8,0.4) J7(-2,0.4) J8(-1.2,0.4) J9(-0.4,0.4) J10(0.4,0.4) J11(1.2,0.4) J12(2,0.4) J13(2.8,0.4) J14(3.6,0.4) J15(4.4,0.4) J16(5.2,0.4) J17(6,0.4) J18(6.8,0.4) K1(-6.8,-0.4) K2(-6,-0.4) K3(-5.2,-0.4) K4(-4.4,-0.4) K5(-3.6,-0.4) K6(-2.8,-0.4) K7(-2,-0.4) K8(-1.2,-0.4) K9(-0.4,-0.4) K10(0.4,-0.4) K11(1.2,-0.4) K12(2,-0.4) K13(2.8,-0.4) K14(3.6,-0.4) K15(4.4,-0.4) K16(5.2,-0.4) K17(6,-0.4) K18(6.8,-0.4) L1(-6.8,-1.2) L2(-6,-1.2) L3(-5.2,-1.2) L4(-4.4,-1.2) L5(-3.6,-1.2) L6(-2.8,-1.2) L7(-2,-1.2) L8(-1.2,-1.2) L9(-0.4,-1.2) L10(0.4,-1.2) L11(1.2,-1.2) L12(2,-1.2) L13(2.8,-1.2) L14(3.6,-1.2) L15(4.4,-1.2) L16(5.2,-1.2) L17(6,-1.2) L18(6.8,-1.2) M1(-6.8,-2) M2(-6,-2) M3(-5.2,-2) M4(-4.4,-2) M5(-3.6,-2) M6(-2.8,-2) M7(-2,-2) M8(-1.2,-2) M9(-0.4,-2) M10(0.4,-2) M11(1.2,-2) M12(2,-2) M13(2.8,-2) M14(3.6,-2) M15(4.4,-2) M16(5.2,-2) M17(6,-2) M18(6.8,-2) N1(-6.8,-2.8) N2(-6,-2.8) N3(-5.2,-2.8) N4(-4.4,-2.8) N5(-3.6,-2.8) N6(-2.8,-2.8) N7(-2,-2.8) N8(-1.2,-2.8) N9(-0.4,-2.8) N10(0.4,-2.8) N11(1.2,-2.8) N12(2,-2.8) N13(2.8,-2.8) N14(3.6,-2.8) N15(4.4,-2.8) N16(5.2,-2.8) N17(6,-2.8) N18(6.8,-2.8) P1(-6.8,-3.6) P2(-6,-3.6) P3(-5.2,-3.6) P4(-4.4,-3.6) P5(-3.6,-3.6) P6(-2.8,-3.6) P7(-2,-3.6) P8(-1.2,-3.6) P9(-0.4,-3.6) P10(0.4,-3.6) P11(1.2,-3.6) P12(2,-3.6) P13(2.8,-3.6) P14(3.6,-3.6) P15(4.4,-3.6) P16(5.2,-3.6) P17(6,-3.6) P18(6.8,-3.6) R1(-6.8,-4.4) R2(-6,-4.4) R3(-5.2,-4.4) R4(-4.4,-4.4) R5(-3.6,-4.4) R6(-2.8,-4.4) R7(-2,-4.4) R8(-1.2,-4.4) R9(-0.4,-4.4) R10(0.4,-4.4) R11(1.2,-4.4) R12(2,-4.4) R13(2.8,-4.4) R14(3.6,-4.4) R15(4.4,-4.4) R16(5.2,-4.4) R17(6,-4.4) R18(6.8,-4.4) T1(-6.8,-5.2) T2(-6,-5.2) T3(-5.2,-5.2) T4(-4.4,-5.2) T5(-3.6,-5.2) T6(-2.8,-5.2) T7(-2,-5.2) T8(-1.2,-5.2) T9(-0.4,-5.2) T10(0.4,-5.2) T11(1.2,-5.2) T12(2,-5.2) T13(2.8,-5.2) T14(3.6,-5.2) T15(4.4,-5.2) T16(5.2,-5.2) T17(6,-5.2) T18(6.8,-5.2) U1(-6.8,-6) U2(-6,-6) U3(-5.2,-6) U4(-4.4,-6) U5(-3.6,-6) U6(-2.8,-6) U7(-2,-6) U8(-1.2,-6) U9(-0.4,-6) U10(0.4,-6) U11(1.2,-6) U12(2,-6) U13(2.8,-6) U14(3.6,-6) U15(4.4,-6) U16(5.2,-6) U17(6,-6) U18(6.8,-6) V1(-6.8,-6.8) V2(-6,-6.8) V3(-5.2,-6.8) V4(-4.4,-6.8) V5(-3.6,-6.8) V6(-2.8,-6.8) V7(-2,-6.8) V8(-1.2,-6.8) V9(-0.4,-6.8) V10(0.4,-6.8) V11(1.2,-6.8) V12(2,-6.8) V13(2.8,-6.8) V14(3.6,-6.8) V15(4.4,-6.8) V16(5.2,-6.8) V17(6,-6.8) V18(6.8,-6.8)
  silkscreen extent -7.82,-7.5 7.5,7.82, body extent -7.55,-7.55 7.55,7.55, height 1.41

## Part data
C1 C91 C92 C94 C95 C97 C98 C100 C101 C103 C104 C106 C107 C108 C109 C110 C111 C112 C113 C114 C119 C120 C121 C122 C124 C125 C126 C127 C128 C129 C130 C134 C135 C145 C146 C149 C150 C151 C152 C153 C154 C155 C156 C157 C158 C159 C160 C161 C163 C164 C165 C166 C167 C169 C182 C183: "CAP, CERM, 0.01 µF, 10 V, +/- 10%, X7R, 0201", Cap_Case=0201, Manufacturer=MuRata, Supplier Part Number 1=490-3194-1-ND, TempCo=X7R, Tolerance_%=10, Value1=Unknown, Value2=10V, ValueDisplayed=0.01µF
C2 C172 C173 C174 C175 C176: "CAP, CERM, 0.1 µF, 10 V, +/- 10%, X7R, 0402", Cap_Case=0402, Manufacturer=MuRata, Supplier Part Number 1=GRM155R71A104KA01D-ND, TempCo=X7R, Tolerance_%=10, Value1=Unknown, Value2=10V, ValueDisplayed=0.1µF
C3 C6 C23 C171: "CAP, CERM, 0.1 µF, 6.3 V, +/- 10%, X7R, 0402", Cap_Case=0402, Manufacturer=MuRata, Supplier Part Number 1=GRM155R70J104KA01D-ND, TempCo=X7R, Tolerance_%=10, Value1=Unknown, Value2=6.3V, ValueDisplayed=0.1µF
C5: "CAP, CERM, 1000 pF, 16 V, +/- 10%, X7R, 0402", Cap_Case=0402, Manufacturer=MuRata, Supplier Part Number 1=GRM155R71C102KA01D-ND, TempCo=X7R, Tolerance_%=10, Value1=Unknown, Value2=16V, ValueDisplayed=1000pF
C7 C8 C32 C36 C55 C63: "CAP, CERM, 10 µF, 10 V, +/- 10%, X7R, 0805", Cap_Case=0805, Manufacturer="Wurth Elektronik", Supplier Part Number 1=710-885012207026, TempCo=X7R, Tolerance_%=10, Value1=Unknown, Value2=10V, ValueDisplayed=10µF
C9 C10 C11 C12 C13 C14 C15 C16 C17 C18 C19 C20 C21 C22 C26 C27 C41 C42 C49 C50 C60 C61 C88 C89 C90: "CAP, CERM, 0.1 µF, 16 V, +/- 10%, X7R, 0402", Cap_Case=0402, Manufacturer="Wurth Elektronik", Supplier Part Number 1=732-7532-1-ND, TempCo=X7R, Tolerance_%=10, Value1=Unknown, Value2=16V, ValueDisplayed=0.1µF
C24 C25 C40 C43 C47 C48 C59 C62 C72 C76 C77 C79 C83 C85 C86 C131 C132 C133: "CAP, CERM, 1 µF, 6.3 V, +/- 20%, X7R, 0402", Cap_Case=0402, Manufacturer=MuRata, Supplier Part Number 1=490-9665-1-ND, TempCo=X7R, Tolerance_%=20, Value1=Unknown, Value2=6.3V, ValueDisplayed=1µF
C28 C29 C30 C31 C51 C52 C53 C54: "CAP, CERM, 4.7 pF, 50 V, +/- 5%, C0G/NP0, 0201", Cap_Case=0201, Manufacturer=MuRata, Supplier Part Number 1=490-6130-1-ND, TempCo=C0G/NP0, Tolerance_%=5, Value1=Unknown, Value2=50V, ValueDisplayed=4.7pF
C33 C37 C56 C64: "CAP, CERM, 0.01 µF, 16 V, +/- 10%, X7R, 0402", Cap_Case=0402, Manufacturer="Wurth Elektronik", Supplier Part Number 1=710-885012205031, TempCo=X7R, Tolerance_%=10, Value1=Unknown, Value2=16V, ValueDisplayed=0.01µF
C34 C38 C57 C65: "CAP, CERM, 1000 pF, 25 V, +/- 10%, X7R, 0402", Cap_Case=0402, Manufacturer="Wurth Elektronik", Supplier Part Number 1=710-885012205044, TempCo=X7R, Tolerance_%=10, Value1=Unknown, Value2=25V, ValueDisplayed=1000pF
C35 C39 C58 C66: "CAP, CERM, 100 pF, 50 V, +/- 10%, X7R, 0402", Cap_Case=0402, Manufacturer="Yageo America", Supplier Part Number 1=311-1419-1-ND, TempCo=X7R, Tolerance_%=10, Value1=Unknown, Value2=50V, ValueDisplayed=100pF
C44 C67: library part CMP-0009320-2, "CAP, CERM, 0.01 uF, 1000 V, +/- 10%, X7R, 1812", Cap_Case=1812, Manufacturer=Kemet, Supplier Part Number 1=399-3450-1-ND, TempCo=X7R, Tolerance_%=10%, Value1=Unknown, Value2=1000V, ValueDisplayed=0.01uF
C45 C46 C68 C69 C168 C170: "CAP, CERM, 20 pF, 50 V, +/- 5%, C0G/NP0, 0402", Cap_Case=0402, Manufacturer=MuRata, Supplier Part Number 1=81-GRM1555C1H200JA01D, TempCo=C0G/NP0, Tolerance_%=5, Value1=Unknown, Value2=50V, ValueDisplayed=20pF
C70 C71 C73 C74 C75 C78 C80 C81 C82 C93 C96 C99 C102 C105 C115 C123 C136 C137 C147 C148 C162: "CAP, CERM, 10 µF, 25 V, +/- 20%, X5R, 0603", Cap_Case=0603, Manufacturer=TDK, Supplier Part Number 1=445-9015-1-ND, TempCo=X5R, Tolerance_%=20, Value1=Unknown, Value2=25V, ValueDisplayed=10µF
C84 C87: "CAP, CERM, 2.2 µF, 10 V, +/- 10%, X7R, 0603", Cap_Case=0603, Manufacturer=MuRata, Supplier Part Number 1=490-4520-1-ND, TempCo=X7R, Tolerance_%=10, Value1="0.009 ohm", Value2=10V, ValueDisplayed=2.2µF
C116 C117 C118 C138 C139 C140 C141 C142 C143 C144: "CAP, CERM, 0.1 µF, 10 V, +/- 10%, X5R, 0201", Cap_Case=0201, Manufacturer=Samsung, Supplier Part Number 1=1276-1115-1-ND, TempCo=X5R, Tolerance_%=10, Value1=Unknown, Value2=10V, ValueDisplayed=0.1µF
C177: "CAP, CERM, 4.7 µF, 16 V, +/- 10%, X5R, 0603", Cap_Case=0603, Manufacturer=MuRata, Supplier Part Number 1=490-10481-1-ND, TempCo=X5R, Tolerance_%=10, Value1=Unknown, Value2=16V, ValueDisplayed=4.7µF
C178 C181: "CAP, CERM, 0.1 µF, 16 V, +/- 10%, X7R, 0603", Cap_Case=0603, Manufacturer=MuRata, Supplier Part Number 1=490-1532-1-ND, TempCo=X7R, Tolerance_%=10, Value1=Unknown, Value2=16V, ValueDisplayed=0.1µF
C179 C180: "CAP, CERM, 22 µF, 10 V, +/- 20%, X5R, 0603", Cap_Case=0603, Manufacturer=MuRata, Supplier Part Number 1=490-10476-1-ND, TempCo=X5R, Tolerance_%=20, Value1=Unknown, Value2=10V, ValueDisplayed=22µF
C184 C186: "CAP, CERM, 1000 pF, 2000 V, +/- 10%, X7R, 1206_190", Cap_Case=1206, Manufacturer="Johanson Technology", TempCo=X7R, Tolerance_%=10, Value1=Unknown, Value2=2000V, ValueDisplayed=1000pF
D2 D3 D8 D15: "LED, Green, SMD", Color=green, Manufacturer="Wurth Elektronik", Supplier Part Number 1=732-4980-1-ND, Value1=W, Value2=2V
D4 D9: "LED, Yellow, SMD", Color=yellow, Manufacturer="Wurth Elektronik", Supplier Part Number 1=732-4981-1-ND, Value1=W, Value2=2V
D5 D10: "LED, Orange, SMD", Color=orange, Manufacturer=Vishay-Semiconductor, Supplier Part Number 1=VLMO1500-GS08CT-ND, Value1=W, Value2=2V
D6 D17: "LED, GREEN SMD", Color=GREEN, Manufacturer=Kingbright, Supplier Part Number 1=754-1949-1-ND
D7: "LED, Red, SMD", Color=Red, Manufacturer="Wurth Elektronik", Power_TotalModule=0.072, Supplier Part Number 1=732-4978-1-ND, Value1=0.072W, Value2=2V
D11 D12 D13 D14: "Diode, Schottky, 40 V, 0.5 A, SOD-123", Manufacturer="ON Semiconductor", Supplier Part Number 1=MBR0540T1GOSCT-ND, Value1=0.5A, Value2=0.51V
D16 D19: "LED, RED SMD", Color=RED, Manufacturer=Kingbright, Supplier Part Number 1=754-1945-1-ND
D18 D20: "LED, YELLOW SMD", Color=YELLOW, Manufacturer=Kingbright, Supplier Part Number 1=754-1947-2-ND
FID1 FID2 FID3 FID4 FID5 FID6: "Fiducial mark.  There is nothing to buy or mount.", Manufacturer=N/A
H1 H2: "Machine Screw, Round, #4-40 x 1/4, Nylon, Philips panhead", DigiKeyPartNumber=H542-ND, Manufacturer="B&F Fastener Supply"
J1: "Header, 1.27mm, 10x2, Tin, SMT", Color=Black, Current_A=3.1, Manufacturer=Samtec, Supplier Part Number 1=SAM8792-ND
J2: "Receptacle, 0.4mm, 30x2, Gold, SMT", Color=Black, Current_A=0.3, Manufacturer="Hirose Electric Co. Ltd.", Supplier Part Number 1=H11918CT-ND, Voltage_V=30
J3: "Header, 100mil, 6x1, Tin, TH", Manufacturer="Sullins Connector Solutions", Supplier Part Number 1=S1012E-06-ND
J4 J5: "Connector, Receptacle, 100mil, 10x2, Gold plated, TH", Manufacturer=Samtec
J6 J7: "RJ-45, No LED, tab up, R/A, TH", Color=Black, Manufacturer="TE Connectivity", Supplier Part Number 1=A97716-ND
J8: "Power Jack, mini, 2.1mm OD, R/A, TH", Manufacturer=Switchcraft, Supplier Part Number 1=SC1313-ND
J9: "Header, 2.54mm, 1x2, Tin, Black, TH", Color=Black, Current_A=3, Manufacturer="Sullins Connector Solutions", Supplier Part Number 1=S2012E-01-ND, Voltage_V=1800
L1 L2: "Inductor, Shielded, Ferrite, 2.2 µH, 1.72 A, 0.059 ohm, SMD", Manufacturer=TDK, Supplier Part Number 1=445-3182-1-ND, Value1="0.059 ohm", Value2=1.72A, ValueDisplayed=2.2µH
L3: "Inductor, Shielded, Ferrite, 3.3 µH, 1.52 A, 0.078 ohm, SMD", Manufacturer=TDK, Supplier Part Number 1=445-3183-1-ND, Value1="0.078 ohm", Value2=1.52A, ValueDisplayed=3.3µH
L4: "Inductor, Shielded, Composite, 1.5 µH, 4.6 A, 0.01 ohm, SMD", Manufacturer=Coilcraft, Supplier Part Number 1=994-XFL4020-152MEB, Value1="0.01 ohm", Value2=4.6A, ValueDisplayed=1.5µH
LBL1: library part THT-14-423-10, "Thermal Transfer Printable Labels, 0.650\" W x 0.200\" H - 10,000 per roll", Alternate Manufacturer=-, Manufacturer=Brady, Supplier Part Number 1=2065596
Logo2: library part Pb-Free
Logo3: library part FCC_disclaimer, "FCC_disclaimer"
Logo4 Logo5: library part ESD_Susceptible, "ESD Susceptible Symbol"
Q1 Q2 Q3 Q4 Q5 Q6: "MOSFET, N-CH, 12 V, 2.9 A, YJC0003A", Alternate Manufacturer=None, Manufacturer="Texas Instruments", Supplier Part Number 1=296-39991-1-ND, Value1="0.044 ohm", Value2="2 nC"
R1 R2 R3 R11 R24 R53 R190 R215 R216 R218 R219 R237: "RES, 4.7 k, 5%, 0.063 W, 0402", Manufacturer=Vishay-Dale, Power_W=0.063, Supplier Part Number 1=541-4.7KJCT-ND, TempCo="200 ppm/C", Tolerance_%=5, Value1=5%, Value2=0.063W, Value_Code=4k70, ValueDisplayed=4.7k
R4 R5 R6 R7 R8 R12 R13 R41 R46 R50 R51 R52 R54 R57 R62 R65 R70 R71 R73 R74 R77 R81 R83 R84 R89 R93 R94 R98 R102 R139 R143 R144 R146 R151 R152 R154 R156 R157 R158 R159 R160 R161 R163 R164 R165 R166 R167 R170 R171 R182 R183 R186 R187 R211 R212: "RES, 0, 5%, 0.063 W, 0402", Manufacturer=Vishay-Dale, Power_W=0.063, Supplier Part Number 1=541-0.0JCT-ND, TempCo="200 ppm/C", Tolerance_%=5, Value1=5%, Value2=0.063W, Value_Code=0000, ValueDisplayed=0
R9: "RES, 100, 5%, 0.063 W, 0402", Manufacturer=Vishay-Dale, Power_W=0.063, Supplier Part Number 1=541-100JCT-ND, TempCo="200 ppm/C", Tolerance_%=5, Value1=5%, Value2=0.063W, Value_Code=100R, ValueDisplayed=100
R10: "RES, 1.0 k, 5%, 0.063 W, 0402", Manufacturer=Vishay-Dale, Power_W=0.063, Supplier Part Number 1=541-1.0KJCT-ND, TempCo="200 ppm/C", Tolerance_%=5, Value1=5%, Value2=0.063W, Value_Code=1k00, ValueDisplayed=1.0k
R14 R18 R23 R32 R33 R48 R55 R64 R76 R103 R104 R105 R106 R107 R108 R109 R110 R111 R112 R113 R114 R115 R116 R117 R118 R119 R120 R121 R138 R141 R142 R162 R168 R207 R208 R209 R210 R213 R214 R234: "RES, 10 k, 5%, 0.063 W, 0402", Manufacturer=Vishay-Dale, Power_W=0.063, Supplier Part Number 1=541-10KJCT-ND, TempCo="200 ppm/C", Tolerance_%=5, Value1=5%, Value2=0.063W, Value_Code=10k0, ValueDisplayed=10k
R15 R17 R25 R27: "RES, 1.6k, 5%, 0.063 W, 0402", Manufacturer=Vishay-Dale, Power_W=0.063, Supplier Part Number 1=541-1.6KJTR-ND, TempCo="200 ppm/c", Tolerance_%=5, Value1=5%, Value2=0.063W, Value_Code=1.6kR, ValueDisplayed=1.6k
R16 R26: "RES, 1.2k, 5%, 0.063 W, 0402", Manufacturer=Vishay-Dale, Power_W=0.063, Supplier Part Number 1=541-1.2KJTR-ND, TempCo="200 ppm/c", Tolerance_%=5, Value1=5%, Value2=0.063W, Value_Code=1.2kR, ValueDisplayed=1.2k
R19 R20 R21 R22 R28 R29 R30 R31: "RES, 1.5 k, 5%, 0.063 W, 0402", Manufacturer=Vishay-Dale, Power_W=0.063, Supplier Part Number 1=541-1.5KJCT-ND, TempCo="200 ppm/C", Tolerance_%=5, Value1=5%, Value2=0.063W, Value_Code=1k50, ValueDisplayed=1.5k
R34 R35 R36 R39 R40 R217 R238 R239 R240: "RES, 10.0 k, 1%, 0.063 W, 0402", Manufacturer=Vishay-Dale, Power_W=0.063, Supplier Part Number 1=541-10.0KLCT-ND, TempCo="100 ppm/C", Tolerance_%=1, Value1=1%, Value2=0.063W, Value_Code=10k0, ValueDisplayed=10.0k
R37: "RES, 1.50 k, 1%, 0.063 W, 0402", Manufacturer=Vishay-Dale, Power_W=0.063, Supplier Part Number 1=541-1.50KLCT-ND, TempCo="100 ppm/C", Tolerance_%=1, Value1=1%, Value2=0.063W, Value_Code=1k50, ValueDisplayed=1.50k
R38: "RES, 240, 1%, 0.1 W, AEC-Q200 Grade 0, 0402", Manufacturer=Panasonic, Power_W=0.1, Supplier Part Number 1=P240LCT-ND, TempCo="100 ppm/C", Tolerance_%=1, Value1=1%, Value2=0.1W, Value_Code=240R, ValueDisplayed=240
R42 R43 R44 R45 R58 R59 R60 R61 R169: "RES, 49.9, 1%, 0.063 W, 0402", Manufacturer=Vishay-Dale, Power_W=0.063, Supplier Part Number 1=541-49.9LCT-ND, TempCo="100 ppm/C", Tolerance_%=1, Value1=1%, Value2=0.063W, Value_Code=49R9, ValueDisplayed=49.9
R47 R63: "RES, 4.87 k, 1%, 0.063 W, 0402", Manufacturer=Vishay-Dale, Power_W=0.063, Supplier Part Number 1=541-4.87KLCT-ND, TempCo="100 ppm/C", Tolerance_%=1, Value1=1%, Value2=0.063W, Value_Code=4k87, ValueDisplayed=4.87k
R49 R66: library part CMP-0016202-1, "RES, 1.00 M, 2%, 0.5 W, 2010", Manufacturer="TT Electronics/IRC", Power_W=500mW, TempCo="100 ppm/C", Tolerance_%=2%, Value2=0.5W, Value_Code=1M00, ValueDisplayed=1.00M
R56 R69: "RES, 2.4 k, 5%, 0.063 W, 0402", Manufacturer=Vishay-Dale, Power_W=0.063, Supplier Part Number 1=541-2.4KJCT-ND, TempCo="200 ppm/C", Tolerance_%=5, Value1=5%, Value2=0.063W, Value_Code=2k40, ValueDisplayed=2.4k
R67 R68 R72 R75 R188 R189 R235 R236: "RES, 2.49 k, 1%, 0.063 W, 0402", Manufacturer=Vishay-Dale, Power_W=0.063, Supplier Part Number 1=541-2.49KLCT-ND, TempCo="100 ppm/C", Tolerance_%=1, Value1=1%, Value2=0.063W, Value_Code=2k49, ValueDisplayed=2.49k
R78: "RES, 165 k, 1%, 0.063 W, 0402", Manufacturer=Vishay-Dale, Power_W=0.063, Supplier Part Number 1=541-165KLCT-ND, TempCo="100 ppm/C", Tolerance_%=1, Value1=1%, Value2=0.063W, Value_Code=165k
R79 R86 R97 R100: "RES, 200 k, 1%, 0.063 W, 0402", Manufacturer=Vishay-Dale, Power_W=0.063, Supplier Part Number 1=541-200KLCT-ND, TempCo="100 ppm/C", Tolerance_%=1, Value1=1%, Value2=0.063W, Value_Code=200k
R80: "RES, 2.0, 5%, 0.1 W, 0603", Manufacturer=Vishay-Dale, Power_W=0.1, Supplier Part Number 1=541-2.0GCT-ND, TempCo="200 ppm/C", Tolerance_%=5, Value1=5%, Value2=0.1W, Value_Code=2R00, ValueDisplayed=2.0
R82: "RES, 301 k, 1%, 0.063 W, 0402", Manufacturer=Vishay-Dale, Power_W=0.063, Supplier Part Number 1=541-301KLCT-ND, TempCo="100 ppm/C", Tolerance_%=1, Value1=1%, Value2=0.063W, Value_Code=301k
R85: "RES, 4.99 k, 1%, 0.063 W, 0402", Manufacturer=Vishay-Dale, Power_W=0.063, Supplier Part Number 1=541-4.99KLCT-ND, TempCo="100 ppm/C", Tolerance_%=1, Value1=1%, Value2=0.063W, Value_Code=4k99, ValueDisplayed=4.99k
R87 R91: "RES, 2.00 k, 1%, 0.063 W, 0402", Manufacturer=Vishay-Dale, Power_W=0.063, Supplier Part Number 1=541-2.00KLCT-ND, TempCo="100 ppm/C", Tolerance_%=1, Value1=1%, Value2=0.063W, Value_Code=2k00, ValueDisplayed=2.00k
R88 R95: "RES, 1.00 k, 1%, 0.063 W, 0402", Manufacturer=Vishay-Dale, Power_W=0.063, Supplier Part Number 1=541-1.00KLCT-ND, TempCo="100 ppm/C", Tolerance_%=1, Value1=1%, Value2=0.063W, Value_Code=1k00, ValueDisplayed=1.00k
R90: "RES, 432 k, 1%, 0.063 W, 0402", Manufacturer=Vishay-Dale, Power_W=0.063, Supplier Part Number 1=541-432KLCT-ND, TempCo="100 ppm/C", Tolerance_%=1, Value1=1%, Value2=0.063W, Value_Code=432k
R92: "RES, 95.3 k, 1%, 0.063 W, 0402", Manufacturer=Vishay-Dale, Power_W=0.063, Supplier Part Number 1=541-95.3KLCT-ND, TempCo="100 ppm/C", Tolerance_%=1, Value1=1%, Value2=0.063W, Value_Code=95k3, ValueDisplayed=95.3k
R96 R99: "RES, 162 k, 1%, 0.063 W, 0402", Manufacturer=Vishay-Dale, Power_W=0.063, Supplier Part Number 1=541-162KLCT-ND, TempCo="100 ppm/C", Tolerance_%=1, Value1=1%, Value2=0.063W, Value_Code=162k
R101 R122 R123 R124 R125 R126 R127 R128 R129 R130 R131 R132 R133 R134 R135 R136 R137 R172: "RES, 100 k, 5%, 0.063 W, 0402", Manufacturer=Vishay-Dale, Power_W=0.063, Supplier Part Number 1=541-100KJCT-ND, TempCo="200 ppm/C", Tolerance_%=5, Value1=5%, Value2=0.063W, Value_Code=100k
R140 R147 R148 R150 R153 R179: "RES, 22, 5%, 0.063 W, 0402", Manufacturer=Vishay-Dale, Power_W=0.063, Supplier Part Number 1=541-22JCT-ND, TempCo="200 ppm/C", Tolerance_%=5, Value1=5%, Value2=0.063W, Value_Code=22R0, ValueDisplayed=22
R145 R149: "RES, 47, 5%, 0.063 W, 0402", Manufacturer=Vishay-Dale, Power_W=0.063, Supplier Part Number 1=541-47JCT-ND, TempCo="200 ppm/C", Tolerance_%=5, Value1=5%, Value2=0.063W, Value_Code=47R0, ValueDisplayed=47
R155: "RES, 2.2 k, 5%, 0.063 W, 0402", Manufacturer=Vishay-Dale, Power_W=0.063, Supplier Part Number 1=541-2.2KJCT-ND, TempCo="200 ppm/C", Tolerance_%=5, Value1=5%, Value2=0.063W, Value_Code=2k20, ValueDisplayed=2.2k
R173 R176 R177: "RES, 51 k, 5%, 0.063 W, 0402", Manufacturer=Vishay-Dale, Power_W=0.063, Supplier Part Number 1=541-51KJCT-ND, TempCo="200 ppm/C", Tolerance_%=5, Value1=5%, Value2=0.063W, Value_Code=51k0, ValueDisplayed=51k
R174 R175: "RES, 33 k, 5%, 0.063 W, 0402", Manufacturer=Vishay-Dale, Power_W=0.063, Supplier Part Number 1=541-33KJCT-ND, TempCo="200 ppm/C", Tolerance_%=5, Value1=5%, Value2=0.063W, Value_Code=33k0, ValueDisplayed=33k
R178: "RES, 3.3 k, 5%, 0.063 W, 0402", Manufacturer=Vishay-Dale, Power_W=0.063, Supplier Part Number 1=541-3.3KJCT-ND, TempCo="200 ppm/C", Tolerance_%=5, Value1=5%, Value2=0.063W, Value_Code=3k30, ValueDisplayed=3.3k
R180 R181: "RES, 10 k, 5%, 0.1 W, 0603", Manufacturer=Vishay-Dale, Power_W=0.1, Supplier Part Number 1=541-10KGCT-ND, TempCo="200 ppm/C", Tolerance_%=5, Value1=5%, Value2=0.1W, Value_Code=10k0, ValueDisplayed=10k
R184 R185: "RES, 1.0 k, 5%, 0.1 W, 0603", Manufacturer=Vishay-Dale, Power_W=0.1, Supplier Part Number 1=541-1.0KGCT-ND, TempCo="200 ppm/C", Tolerance_%=5, Value1=5%, Value2=0.1W, Value_Code=1k00, ValueDisplayed=1.0k
R191 R192 R193 R194 R195 R196 R197 R198 R199 R200 R201 R202 R203 R204 R205 R206: "RES, 1.00 k, 1%, 0.05 W, 0201", Manufacturer=Vishay-Dale, Power_W=0.05, Supplier Part Number 1=541-1.00KAABCT-ND, TempCo="100 ppm/C", Tolerance_%=1, Value1=1%, Value2=0.05W, Value_Code=1k00, ValueDisplayed=1.00k
R220 R221 R222 R223 R224 R225 R226 R227: "RES, 75.0, 1%, 0.125 W, 0805", Manufacturer=Vishay-Dale, Power_W=0.125, Supplier Part Number 1=541-75.0CCT-ND, TempCo="100 ppm/C", Tolerance_%=1, Value1=1%, Value2=0.125W, Value_Code=75R0, ValueDisplayed=75.0
R228 R229 R230 R231 R232 R233: "RES, 499, 1%, 0.05 W, 0201", Manufacturer=Vishay-Dale, Power_W=0.05, Supplier Part Number 1=541-499AABCT-ND, TempCo="100 ppm/C", Tolerance_%=1, Value1=1%, Value2=0.05W, Value_Code=499R, ValueDisplayed=499
S1: "SWITCH TACTILE SPST-NO 0.05A 12V", CurrentRating_mA=50, Manufacturer="Omron Electronic Components", Supplier Part Number 1=SW1020CT-ND
T1 T2: "Transformer, 350 uH, SMT", Manufacturer="Pulse Engineering", Supplier Part Number 1=553-2208-1-ND, ValueDisplayed=350µH
TP8 TP9 TP10: "Test Point, Miniature, Black, TH", Color=Black, Manufacturer=Keystone, Supplier Part Number 1=36-5001-ND
U1: "4GBIT DDR3 SDRAM, 96-FBGA", Manufacturer="Micron Technology", Supplier Part Number 1="MT41K256M16HA-125 IT:E-ND"
U2: "3V 64 M-bit Serial Flash Memory With Dual/Quad SPI&QPI, WSON-8", Manufacturer=Winbond, Supplier Part Number 1=W25Q64FVZPIG-ND
U3 U5: library part DP83822RHBR, "10/100 Ethernet PHY, RHB0032B", Alternate Manufacturer="Texas Instruments", Alternate PartNumber=DP83822RHBT
U4 U6: "1, 4, 6 CHANNEL PROTECTION SOLUTION FOR SUPER-SPEED (UP TO 6 GBPS) INTERFACE, DQA0010A", Alternate Manufacturer="Texas Instruments"
U7: "Power Management IC for Li-Ion Powered Systems, RHB0032E", Alternate Manufacturer="Texas Instruments", Alternate PartNumber=TPS650250RHBT
U8 U9: "Octal Buffers/Drivers With 3-State Outputs, DGV0020A", Alternate Manufacturer="Texas Instruments"
U10: "Dual Bilateral Analog Switch, YZP0008ADAD", Alternate Manufacturer="Texas Instruments"
U11: "Sitara Processors, ZCZ0324A", Alternate Manufacturer=None, Manufacturer="Texas Instruments"
U12: "Dual Buffer and Driver With 3-State Output, YZP0008ADAD", Alternate Manufacturer="Texas Instruments"
U13 U14 U15: "8-BIT FET BUS SWITCH 2.5-V/3.3-V LOW-VOLTAGE HIGH-BANDWIDTH BUS SWITCH, RGY0020A", Alternate Manufacturer="Texas Instruments"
